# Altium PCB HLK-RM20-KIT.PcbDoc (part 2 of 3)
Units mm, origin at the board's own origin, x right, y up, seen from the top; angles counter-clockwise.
Board outline 152 x 109 mm, 2 copper layers (Top Layer, Bottom Layer), stack 0.325 mm thick; 212 components, 285 nets, 988 pads, 747 vias.
Unrouted connection lines stored in the file: 195.
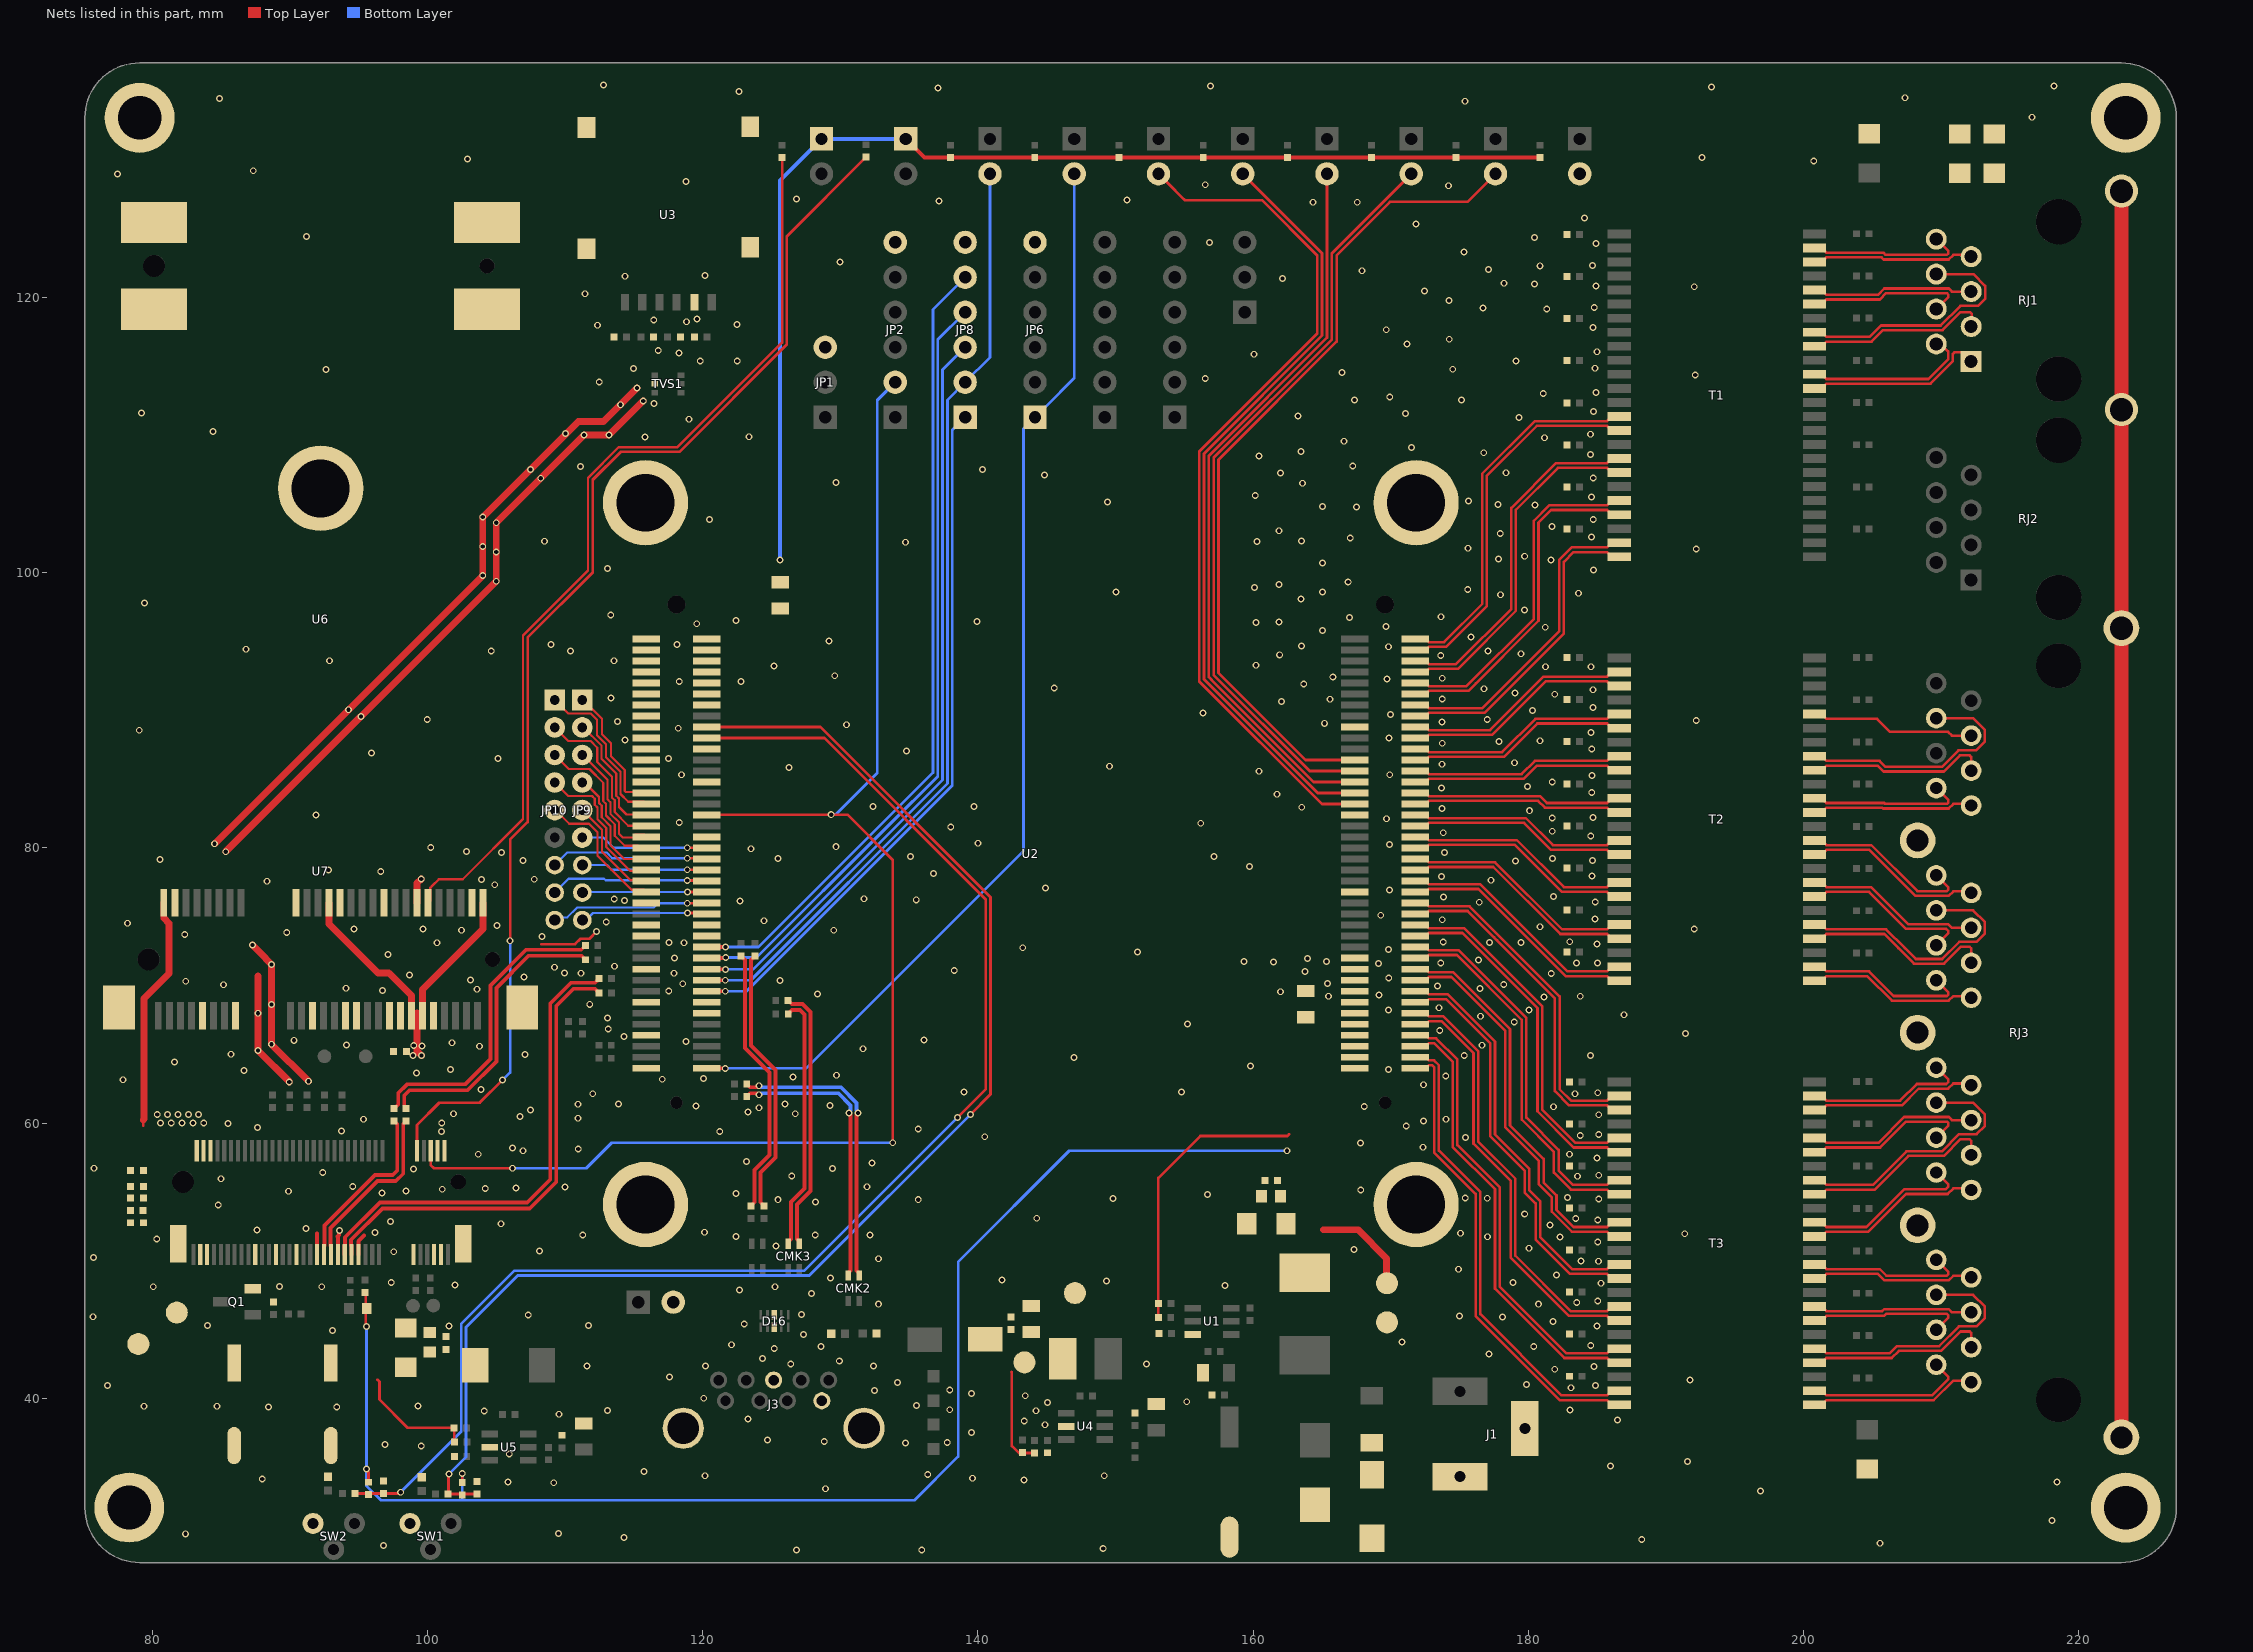
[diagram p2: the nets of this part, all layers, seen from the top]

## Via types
v1: diameter 0.5, hole 0.3, Top Layer to Bottom Layer, tented both sides, 747 vias

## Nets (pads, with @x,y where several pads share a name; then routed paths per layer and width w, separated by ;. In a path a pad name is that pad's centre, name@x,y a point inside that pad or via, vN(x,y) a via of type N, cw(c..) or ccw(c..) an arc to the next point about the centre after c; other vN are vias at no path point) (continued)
5G_SSUSB_RX_N: R64.1 U7.29 | length 34.3
  Top Layer w0.283: U7.29@94.475,50.45 94.475,51.075 94.443,51.107 94.443,51.519 96.721,53.797 107.423,53.797 109.351,55.725 109.351,68.519 110.594,69.762 112.154,69.762 112.343,69.574 R64.1@112.451,69.466
5G_SSUSB_RX_P: R65.1 U7.31 | length 35
  Top Layer w0.283: U7.31@93.975,50.45 93.975,51.075 94.007,51.107 94.007,51.699 96.541,54.233 107.242,54.233 108.915,55.905 108.915,68.699 110.414,70.198 112.177,70.198 112.343,70.364 112.343,70.386 R65.1@112.451,70.495
5G_SSUSB_TX_N: C68.1 R66.1 | length 21.3
  Top Layer w0.283: 98.304,61.354 98.304,61.995 98.691,62.382 102.908,62.382 104.994,64.469 104.994,69.828 107.328,72.162 111.173,72.162 R66.1@111.467,71.868
5G_SSUSB_TX_P: C67.1 R67.1 | length 22.4
  Top Layer w0.283: C67.1@97.574,61.062 97.869,61.357 97.869,62.176 98.511,62.818 102.727,62.818 104.559,64.649 104.559,70.009 107.147,72.597 111.164,72.597 R67.1@111.462,72.895
5G_USB_TX_N: C68.2 U7.35 | length 12.8
  Top Layer w0.283: U7.35@92.975,50.45 92.975,51.075 92.943,51.107 92.943,52.37 96.351,55.778 97.687,55.778 98.228,56.319 98.228,59.931 C68.2@98.447,60.15
5G_USB_TX_P: C67.2 U7.37 | length 12.7
  Top Layer w0.283: U7.37@92.475,50.45 92.475,51.075 92.507,51.107 92.507,52.551 96.171,56.214 97.466,56.214 97.793,56.541 97.793,59.928 C67.2@97.574,60.147
+3.3V: C2.2 C6.2 C8.2 C9.2 C10.1 C28.1 D14.1 D19.1 D20.1 L1.2 R2.1 R13.2 R16.1 R17.2 R20.2 R23.2 R26.2 R28.2 R29.1 R31.2 R34.2 R35.2 TP4.1 U2.A1 U2.A3 U2.A5 U2.A7 U2.A9 U2.A11 U2.B63 U2.B65 U2.B67 U2.B69 U2.B71 U2.B73 U2.B75 U2.B77 U2.B79 | length 216.7
  Top Layer w0.2: R28.2@95.463,47.689 95.509,47.643 95.509,45.258 v1(95.555,45.212) ; v1(95.555,34.849) 95.555,34.768 95.706,34.617 R29.1@95.706,33.9 ; R16.1@102.515,33.87 v1(102.514,34.544) ; R2.1@153.104,45.877 153.104,56 156.159,59.055 162.484,59.055 162.611,59.182
  Top Layer w0.3: D20.1@134.748,131.521 136.106,130.163 R35.2@138.002,130.163 R34.2@144.124,130.163 R31.2@150.245,130.163 R26.2@156.367,130.163 R23.2@162.488,130.163 R20.2@168.609,130.163 R17.2@174.731,130.163 R13.2@180.852,130.163
  Top Layer w0.5: 165.1,52.248 167.615,52.248 169.697,50.165 169.697,48.387 TP4.1@169.723,48.362
  Bottom Layer w0.2: v1(95.555,45.212) v1(95.555,34.849) 95.555,33.638 96.604,32.588 102.511,32.588 ; v1(102.514,34.544) 102.511,34.541 102.511,32.588 ; v1(162.458,57.988) 146.634,57.988 138.557,49.911 138.557,35.763 135.382,32.588 102.511,32.588
  Bottom Layer w0.3: v1(125.603,100.914) 125.603,128.499 D14.1@128.626,131.521 D20.1@134.748,131.521
+3.8V: C17.1 C20.2 C21.2 C22.1 C31.1 C61.1 C62.1 C63.1 C64.1 C65.1 C66.1 D15.2 L2.2 R6.1 TP1.1 U6.2 U6.24 U6.39 U6.41 U6.52 U7.2 U7.4 U7.70 U7.72 U7.74 | length 50.3
  Top Layer w0.2: 79.337,59.817 79.337,60.223 ; 96.355,41.351 96.507,41.199 96.507,39.903 98.56,37.85 R6.1@101.918,37.85 101.938,37.83 101.938,36.855 C20.2@101.957,36.836
  Top Layer w0.5: 79.337,60.223 79.401,60.288 79.401,69.051 81.212,70.862 81.212,74.519 80.829,74.902 80.829,75.996 U6.2@80.825,76 ; U6.24@92.825,76 92.825,74.472 96.393,70.904 97.18,70.904 98.821,69.263 U6.39@98.821,67.804 ; 99.225,67.996 99.225,65.223 v1(99.547,64.9) ; U6.41@99.625,67.8 99.625,69.702 104.025,74.102 U6.52@104.025,76
  other v1: 101.011,59.392 80.581,59.995 81.368,59.995 82.155,59.995 82.942,59.995 83.729,59.995 101.031,60.001 80.352,60.613 81.105,60.613 81.858,60.613 82.611,60.613 83.364,60.613 98.945,64.904 99.598,65.607 98.995,65.63
+4.5V~18V: D1.1 D2.2 F2.2
+5V: C23.2 C24.2 C25.1 D3.1 L4.2 R10.1 TP7.1 | length 7.3
  Top Layer w0.2: 142.443,41.91 142.46,41.893 142.46,36.536 142.971,36.026 143.23,36.026 R10.1@144.119,36.026
DZSS_RX_N: CMK3.1 R71.1 | length 19.3
  Top Layer w0.283: R71.1@126.205,68.915 126.313,68.806 126.313,68.805 126.479,68.639 127.252,68.639 127.816,68.075 127.816,55.058 126.837,54.078 126.837,51.586 127.019,51.404 CMK3.1@127.019,51.229
DZSS_RX_P: CMK3.2 R70.1 | length 18.6
  Top Layer w0.283: R70.1@126.206,67.928 126.314,68.037 126.314,68.038 126.48,68.204 127.071,68.204 127.381,67.894 127.381,55.238 126.401,54.258 126.401,51.585 126.219,51.403 CMK3.2@126.219,51.229
DZSS_TX_N: C33.2 R69.1 | length 19.6
  Top Layer w0.283: R69.1@123.796,72.137 123.687,72.029 123.667,72.029 123.501,71.863 123.501,65.631 125.276,63.856 125.276,57.498 124.197,56.419 124.197,54.247 C33.2@124.458,53.986
DZSS_TX_P: C32.2 R68.1 | length 19.6
  Top Layer w0.283: R68.1@122.771,72.137 122.879,72.029 122.9,72.029 123.066,71.863 123.066,65.451 124.841,63.675 124.841,57.678 123.762,56.599 123.762,54.247 C32.2@123.501,53.986
DZUSB_D_N: CMK2.3 R72.2 | length 21.2
  Top Layer w0.283: R72.2@123.193,62.844 123.432,62.604 123.914,62.604 124.023,62.713 v1(124.082,62.713) ; v1@131.18,60.577 131.18,49.274 131.362,49.092 CMK2.3@131.362,48.917
  Bottom Layer w0.283: v1(124.082,62.713) 124.14,62.713 124.249,62.604 130.044,62.604 131.18,61.468 131.18,60.911 131.289,60.803 v1(131.289,60.744)
DZUSB_D_P: CMK2.4 R73.2 | length 20.6
  Top Layer w0.283: R73.2@123.193,61.929 123.432,62.169 123.914,62.169 124.023,62.06 v1(124.082,62.06) ; CMK2.4@130.563,48.917 130.563,49.092 130.745,49.274 130.745,60.577 130.636,60.685 v1(130.636,60.744)
  Bottom Layer w0.283: v1(124.082,62.06) 124.14,62.06 124.249,62.169 129.864,62.169 130.745,61.288 130.745,60.911 130.636,60.803 v1(130.636,60.744)
ESW_A_P1_TXV_N: T3.23 U2.A4 | length 34
  Top Layer w0.188: U2.A4@171.786,64.783 172.536,64.783 172.766,64.553 173.141,64.553 173.492,64.202 173.492,58.008 176.512,54.988 176.512,46.108 182.415,40.206 185.728,40.206 185.838,40.316 185.838,40.319 186.064,40.545 T3.23@186.594,40.545
ESW_A_P1_TXV_P: T3.24 U2.A2 | length 33.8
  Top Layer w0.188: U2.A2@171.786,63.983 172.536,63.983 172.766,64.213 173,64.213 173.152,64.061 173.152,57.867 176.171,54.847 176.171,46.123 176.171,45.967 182.274,39.865 185.728,39.865 185.838,39.755 185.838,39.751 186.064,39.525 T3.24@186.453,39.525
ESW_A_P2_TXV_N: T3.11 U2.A20 | length 28.4
  Top Layer w0.188: U2.A20@171.786,71.183 172.536,71.183 172.766,70.953 174.547,70.953 178.664,66.836 178.664,59.836 181.101,57.399 181.101,55.689 182.042,54.749 182.042,53.696 183.292,52.446 185.728,52.446 185.838,52.556 185.838,52.559 186.064,52.785 T3.11@186.594,52.785
ESW_A_P2_TXV_P: T3.12 U2.A18 | length 28.4
  Top Layer w0.188: U2.A18@171.786,70.383 172.536,70.383 172.766,70.613 174.406,70.613 178.323,66.695 178.323,59.695 180.761,57.258 180.761,55.548 181.701,54.608 181.701,53.555 183.151,52.105 185.728,52.105 185.838,51.995 185.838,51.991 186.064,51.765 T3.12@186.594,51.765
ESW_A_P3_TXV_N: T2.23 U2.A36 | length 17.7
  Top Layer w0.188: U2.A36@171.786,77.583 172.536,77.583 172.766,77.353 176.514,77.353 182.847,71.021 185.728,71.021 185.838,71.131 185.838,71.134 186.064,71.36 T2.23@186.594,71.36
ESW_A_P3_TXV_P: T2.24 U2.A34 | length 17.7
  Top Layer w0.188: U2.A34@171.786,76.783 172.536,76.783 172.766,77.013 176.373,77.013 182.706,70.68 185.728,70.68 185.838,70.57 185.838,70.566 186.064,70.34 T2.24@186.594,70.34
ESW_A_P4_TXV_N: T2.11 U2.A52 | length 15.3
  Top Layer w0.188: U2.A52@171.786,83.983 172.536,83.983 172.766,83.753 180.853,83.753 181.346,83.261 185.728,83.261 185.838,83.371 185.838,83.374 186.064,83.6 T2.11@186.594,83.6
ESW_A_P4_TXV_P: T2.12 U2.A50 | length 15.3
  Top Layer w0.188: U2.A50@171.786,83.183 172.536,83.183 172.766,83.413 180.712,83.413 181.205,82.92 185.728,82.92 185.838,82.81 185.838,82.806 186.064,82.58 T2.12@186.594,82.58
ESW_A_P5_TXV_N: T1.23 U2.A68 | length 22.9
  Top Layer w0.188: U2.A68@171.786,90.383 172.536,90.383 172.766,90.153 176.653,90.153 182.235,95.735 182.235,100.928 183.142,101.836 185.728,101.836 185.838,101.946 185.838,101.949 186.064,102.175 T1.23@186.594,102.175
ESW_A_P5_TXV_P: T1.24 U2.A66 | length 22.9
  Top Layer w0.188: U2.A66@171.786,89.583 172.536,89.583 172.766,89.813 176.794,89.813 182.575,95.594 182.575,100.787 183.283,101.495 185.728,101.495 185.838,101.385 185.838,101.381 186.064,101.155 T1.24@186.594,101.155
ESW_B_P1_TXV_N: T3.20 U2.A8 | length 32.4
  Top Layer w0.188: U2.A8@171.786,66.383 172.536,66.383 172.766,66.153 173.296,66.153 174.84,64.609 174.84,58.41 177.912,55.338 177.912,48.115 182.761,43.266 185.728,43.266 185.838,43.376 185.838,43.379 186.064,43.605 T3.20@186.594,43.605
ESW_B_P1_TXV_P: T3.21 U2.A6 | length 32.4
  Top Layer w0.188: U2.A6@171.786,65.583 172.536,65.583 172.766,65.813 173.155,65.813 174.5,64.468 174.5,58.269 177.571,55.197 177.571,47.974 182.62,42.925 185.728,42.925 185.838,42.815 185.838,42.811 186.064,42.585 T3.21@186.594,42.585
ESW_B_P2_TXV_N: T3.8 U2.A24 | length 27.2
  Top Layer w0.188: U2.A24@171.786,72.783 172.536,72.783 172.766,72.553 174.947,72.553 179.857,67.643 179.857,60.393 182.194,58.056 182.194,56.54 183.229,55.506 185.728,55.506 185.838,55.616 185.838,55.619 186.064,55.845 T3.8@186.594,55.845
ESW_B_P2_TXV_P: T3.9 U2.A22 | length 27.2
  Top Layer w0.188: U2.A22@171.786,71.983 172.536,71.983 172.766,72.213 174.806,72.213 179.517,67.502 179.517,60.252 181.854,57.915 181.854,56.399 183.088,55.165 185.728,55.165 185.838,55.055 185.838,55.051 186.064,54.825 T3.9@186.594,54.825
ESW_B_P3_TXV_N: T2.20 U2.A40 | length 17.1
  Top Layer w0.188: U2.A40@171.786,79.183 172.536,79.183 172.766,78.953 177.587,78.953 182.459,74.081 185.728,74.081 185.838,74.191 185.838,74.194 186.064,74.42 T2.20@186.594,74.42
ESW_B_P3_TXV_P: T2.21 U2.A38 | length 17.1
  Top Layer w0.188: U2.A38@171.786,78.383 172.536,78.383 172.766,78.613 177.446,78.613 182.318,73.74 185.728,73.74 185.838,73.63 185.838,73.626 186.064,73.4 T2.21@186.594,73.4
ESW_B_P4_TXV_N: T2.8 U2.A56 | length 15.4
  Top Layer w0.188: U2.A56@171.786,85.583 172.536,85.583 172.766,85.353 179.511,85.353 180.478,86.321 185.728,86.321 185.838,86.431 185.838,86.434 186.064,86.66 T2.8@186.594,86.66
ESW_B_P4_TXV_P: T2.9 U2.A54 | length 15.4
  Top Layer w0.188: U2.A54@171.786,84.783 172.536,84.783 172.766,85.013 179.652,85.013 180.619,85.98 185.728,85.98 185.838,85.87 185.838,85.866 186.064,85.64 T2.9@186.594,85.64
ESW_B_P5_TXV_N: T1.20 U2.A72 | length 24.7
  Top Layer w0.188: U2.A72@171.786,91.983 172.536,91.983 172.766,91.753 175.497,91.753 180.391,96.647 180.391,103.773 181.513,104.896 185.728,104.896 185.838,105.006 185.838,105.009 186.064,105.235 T1.20@186.594,105.235
ESW_B_P5_TXV_P: T1.21 U2.A70 | length 25.6
  Top Layer w0.188: U2.A70@171.786,91.183 172.536,91.183 172.766,91.413 175.638,91.413 ; 176.189,91.964 175.638,91.413 ; T1.21@186.735,104.215 T1.21@186.594,104.215 186.064,104.215 185.838,104.441 185.838,104.445 185.728,104.555 181.654,104.555 180.731,103.632 180.731,96.506 175.638,91.413
ESW_C_P1_TXV_N: T3.17 U2.A12 | length 31
  Top Layer w0.188: U2.A12@171.786,67.983 172.536,67.983 172.766,67.753 173.823,67.753 176.352,65.224 176.352,64.237 ; 176.352,64.237 176.352,58.648 179.045,55.955 179.045,50.368 183.076,46.337 183.087,46.326 185.728,46.326 185.838,46.436 185.838,46.439 186.064,46.665 T3.17@186.594,46.665
ESW_C_P1_TXV_P: T3.18 U2.A10 | length 31
  Top Layer w0.188: U2.A10@171.786,67.183 172.536,67.183 172.766,67.413 173.682,67.413 176.012,65.083 176.012,64.096 176.012,58.507 178.704,55.814 178.704,50.227 178.804,50.128 182.946,45.985 185.728,45.985 185.838,45.875 185.838,45.871 186.064,45.645 T3.18@186.594,45.645
ESW_C_P2_TXV_N: T3.5 U2.A28 | length 25.9
  Top Layer w0.188: U2.A28@171.786,74.383 172.536,74.383 172.766,74.153 175.347,74.153 181,68.5 181,61 183.434,58.566 185.728,58.566 185.838,58.676 185.838,58.679 186.064,58.905 T3.5@186.594,58.905
ESW_C_P2_TXV_P: T3.6 U2.A26 | length 25.8
  Top Layer w0.188: U2.A26@171.786,73.583 172.536,73.583 172.766,73.813 175.206,73.813 180.66,68.359 180.66,60.859 183.293,58.225 185.728,58.225 185.838,58.115 185.838,58.111 186.064,57.885 T3.6@186.453,57.885
ESW_C_P3_TXV_N: T2.17 U2.A44 | length 16.5
  Top Layer w0.188: U2.A44@171.786,80.783 172.536,80.783 172.766,80.553 179.162,80.553 182.574,77.141 185.728,77.141 185.838,77.251 185.838,77.254 186.064,77.48 T2.17@186.594,77.48
ESW_C_P3_TXV_P: T2.18 U2.A42 | length 16.5
  Top Layer w0.188: U2.A42@171.786,79.983 172.536,79.983 172.766,80.213 179.021,80.213 182.433,76.8 185.728,76.8 185.838,76.69 185.838,76.686 186.064,76.46 T2.18@186.594,76.46
ESW_C_P4_TXV_N: T2.5 U2.A60 | length 16.1
  Top Layer w0.188: U2.A60@171.786,87.183 172.536,87.183 172.766,86.953 178.089,86.953 180.516,89.381 185.728,89.381 185.838,89.491 185.838,89.494 186.064,89.72 T2.5@186.594,89.72
ESW_C_P4_TXV_P: T2.6 U2.A58 | length 16.1
  Top Layer w0.188: U2.A58@171.786,86.383 172.536,86.383 172.766,86.613 178.23,86.613 180.657,89.04 185.728,89.04 185.838,88.93 185.838,88.926 186.064,88.7 T2.6@186.594,88.7
ESW_C_P5_TXV_N: T1.17 U2.A76 | length 25.4
  Top Layer w0.188: U2.A76@171.786,93.583 172.536,93.583 172.766,93.353 174.735,93.353 178.755,97.373 178.755,104.714 181.997,107.956 185.728,107.956 185.838,108.066 185.838,108.069 186.064,108.295 T1.17@186.594,108.295
ESW_C_P5_TXV_P: T1.18 U2.A74 | length 25.4
  Top Layer w0.188: U2.A74@171.786,92.783 172.536,92.783 172.766,93.013 174.876,93.013 179.095,97.232 179.095,104.573 182.138,107.615 185.728,107.615 185.838,107.505 185.838,107.501 186.064,107.275 T1.18@186.594,107.275
ESW_D_P1_TXV_N: T3.14 U2.A16 | length 29.7
  Top Layer w0.188: U2.A16@171.786,69.583 172.536,69.583 172.766,69.353 174.147,69.353 177.571,65.929 177.571,59.179 180.071,56.679 180.071,55.107 180.873,54.305 180.873,51.689 183.177,49.386 185.728,49.386 185.838,49.496 185.838,49.499 186.064,49.725 T3.14@186.594,49.725
ESW_D_P1_TXV_P: T3.15 U2.A14 | length 29.7
  Top Layer w0.188: U2.A14@171.786,68.783 172.536,68.783 172.766,69.013 174.006,69.013 177.231,65.788 177.231,59.038 179.731,56.538 179.731,54.966 180.533,54.164 180.533,51.548 183.036,49.045 185.728,49.045 185.838,48.935 185.838,48.931 186.064,48.705 T3.15@186.594,48.705
ESW_D_P2_TXV_N: T3.2 U2.A32 | length 24.9
  Top Layer w0.188: U2.A32@171.786,75.983 172.536,75.983 172.766,75.753 175.728,75.753 182.27,69.211 182.27,62.459 183.104,61.626 185.728,61.626 185.838,61.736 185.838,61.739 186.064,61.965 T3.2@186.594,61.965
ESW_D_P2_TXV_P: T3.3 U2.A30 | length 24.9
  Top Layer w0.188: U2.A30@171.786,75.183 172.536,75.183 172.766,75.413 175.587,75.413 177.5,73.5 177.73,73.27 181.93,69.07 181.93,62.318 182.963,61.285 185.728,61.285 185.838,61.175 185.838,61.171 186.064,60.945 T3.3@186.594,60.945
ESW_D_P3_TXV_N: T2.14 U2.A48 | length 15.9
  Top Layer w0.188: U2.A48@171.786,82.383 172.536,82.383 172.766,82.153 179.822,82.153 181.775,80.201 185.728,80.201 185.838,80.311 185.838,80.314 186.064,80.54 T2.14@186.594,80.54
ESW_D_P3_TXV_P: T2.15 U2.A46 | length 15.9
  Top Layer w0.188: U2.A46@171.786,81.583 172.536,81.583 172.766,81.813 179.681,81.813 181.634,79.86 185.728,79.86 185.838,79.75 185.838,79.746 186.064,79.52 T2.15@186.594,79.52
ESW_D_P4_TXV_N: T2.2 U2.A64 | length 16.7
  Top Layer w0.188: U2.A64@171.786,88.783 172.536,88.783 172.766,88.553 177.225,88.553 181.112,92.441 185.728,92.441 185.838,92.551 185.838,92.554 186.064,92.78 T2.2@186.594,92.78
ESW_D_P4_TXV_P: T2.3 U2.A62 | length 16.7
  Top Layer w0.188: U2.A62@171.786,87.983 172.536,87.983 172.766,88.213 177.366,88.213 181.253,92.1 185.728,92.1 185.838,91.99 185.838,91.986 186.064,91.76 T2.3@186.594,91.76
ESW_D_P5_TXV_N: T1.14 U2.A80 | length 27.2
  Top Layer w0.188: U2.A80@171.786,95.183 172.536,95.183 172.766,94.953 173.872,94.953 176.647,97.728 176.647,107.197 180.466,111.016 185.728,111.016 185.838,111.126 185.838,111.129 186.064,111.355 T1.14@186.594,111.355
ESW_D_P5_TXV_P: T1.15 U2.A78 | length 27.2
  Top Layer w0.188: U2.A78@171.786,94.383 172.536,94.383 172.766,94.613 174.013,94.613 176.987,97.587 176.987,107.056 180.607,110.675 185.728,110.675 185.838,110.565 185.838,110.561 186.064,110.335 T1.15@186.594,110.335
ESW_P1_LED: D5.2 U2.A57 | length 60.4
  Top Layer w0.2: U2.A57@167.386,86.383 163.807,86.383 157.48,92.71 157.48,108.204 166.066,116.79 166.066,123.065 169.95,126.949 175.574,126.949 D5.2@177.606,128.981
ESW_P2_LED: D6.2 U2.A55 | length 55.5
  Top Layer w0.2: U2.A55@167.386,85.583 164.108,85.583 157.128,92.564 157.128,108.35 165.713,116.936 165.713,123.211 D6.2@171.484,128.981
ESW_P3_LED: D8.2 U2.A53 | length 53.9
  Top Layer w0.2: D8.2@165.361,128.981 165.361,117.082 156.775,108.496 156.775,92.418 156.972,92.221 156.972,92.202 164.391,84.783 U2.A53@167.386,84.783
ESW_P4_LED_0: D9.2 U2.A51 | length 57.1
  Top Layer w0.2: D9.2@159.238,128.981 165.009,123.211 165.009,117.228 156.423,108.642 156.423,92.253 164.692,83.983 U2.A51@167.386,83.983
ESW_P5_LED_0: D10.2 U2.A49 | length 63.5
  Top Layer w0.2: D10.2@153.116,128.981 153.752,128.345 154.965,127.132 155.024,127.073 155.107,127.073 160.648,127.073 164.656,123.065 164.656,117.374 156.07,108.788 156.07,92.107 164.994,83.183 U2.A49@167.386,83.183
FULL_CARD_POWER_OFF#: JP2.2 U2.B48 U7.6 | length 104.5
  Top Layer w0.2: U7.6@100.225,58 100.225,56.963 100.469,56.718 v1(106.165,56.718) ; U2.B48@120.286,82.383 120.315,82.412 v1(129.331,82.412) 130.516,82.412 133.807,79.121 v1(133.807,58.572)
  Bottom Layer w0.2: v1(106.165,56.718) 111.531,56.718 113.386,58.572 v1(133.807,58.572) ; v1(129.331,82.412) 129.361,82.442 129.678,82.442 132.675,85.438 132.675,112.533 JP2.2@133.985,113.843
GBE_LED0: D13.2 JP8.2 U2.B18 | length 69
  Top Layer w0.283: U2.B18@120.286,70.383 121.628,70.383 v1(121.634,70.377)
  Bottom Layer w0.2: v1(121.634,70.377) 123.482,70.377 137.78,84.675 137.78,112.557 JP8.2@139.065,113.843 140.871,115.649 D13.2@140.871,128.981
GBE_LED1: D11.2 JP6.1 U2.B2 | length 80.3
  Top Layer w0.283: U2.B2@120.286,63.983 121.628,63.983 v1(121.634,63.977)
  Bottom Layer w0.2: v1(121.634,63.977) 127.489,63.977 143.299,79.787 143.299,110.457 144.895,112.053 146.993,114.151 D11.2@146.993,128.981
GND: C2.1 C3.2 C4.1 C5.2 C6.1 C9.1 C10.2 C11.2 C12.2 C13.2 C14.1 C16.2 C17.2 C18.1 C19.2 C21.1 C22.2 C24.1 C25.2 C26.1 C27.1 C28.2 C30.1 C31.2 C34.2 C35.1 C36.1 C37.1 C38.1 C39.1 C40.1 C41.1 C42.1 C43.1 C44.1 C45.1 C46.1 C47.1 C48.1 C49.1 C50.1 C51.1 C52.1 C53.1 C54.1 C55.1 C56.1 C57.1 C58.1 C59.1 C60.2 C61.2 C62.2 C63.2 C64.2 C65.2 C66.2 D2.1 D4.2 D7.1 D12.1 D15.1 D16.3 D16.8 D17.1 D18.1 J1.2 J1.3 J3.4 J3.7 J3.10 J3.11 J5.1 J6.1 J7.1 J8.1 JP1.3 JP2.6 JP5.2 JP6.6 JP8.6 Q1.2 R5.2 R7.2 R12.2 R14.1 R44.1 SW1.1 SW2.1 TP2.1 TP6.1 TP10.1 TVS1.2 U1.3 U2.0 U2.A13 U2.A15 U2.A17 U2.A19 U2.A21 U2.A33 U2.A47 U2.A63 U2.B1 U2.B7 U2.B12 U2.B13 U2.B14 U2.B19 U2.B25 U2.B26 U2.B27 U2.B28 U2.B31 U2.B44 U2.B53 U2.B54 U2.B55 U2.B57 U2.B59 U2.B60 U2.B61 U2.B68 U2.B70 U2.B72 U2.B74 U2.B76 U2.B78 U2.B80 U3.0 U3.1 U4.2 U5.2 U6.4 U6.9 U6.15 U6.18 U6.21 U6.26 U6.27 U6.29 U6.34 U6.35 U6.37 U6.40 U6.43 U6.50 U6.55 U6.56 U6.63 U6.64 U6.65 U6.66 U7.0 U7.3 U7.5 U7.11 U7.27 U7.33 U7.39 U7.45 U7.51 U7.57 U7.71 U7.73 U7.76 U7.77 | length 124.7
  Top Layer w0.2: 108.254,73 110.71,73 111.107,73.397 111.751,73.397 v1(112.268,73.914)
  Top Layer w0.3: 91.973,51.968 91.975,51.967 U7.39@91.975,50.45 ; U7.33@93.475,50.45 93.475,51.762 93.472,51.765 93.561,51.854 93.561,52.159 v1(93.599,52.197) ; U7.27@94.975,50.45 94.975,51.414 95.377,51.816
  Top Layer w0.5: v1(84.518,80.296) v1(104.009,99.787) v1(104.009,104.039) 110.951,110.981 112.787,110.981 v1(115.228,113.422) ; v1(85.331,79.719) v1(104.991,99.38) v1(104.991,103.632) v1(111.358,109.999) v1(113.194,109.999) v1(115.669,112.474) ; v1(87.266,72.928) 88.249,71.945 88.249,71.936 v1(88.667,71.517) v1(88.667,65.727) v1(91.351,63.043) ; 87.685,70.688 v1(87.685,65.274) 89.946,63.013 v1(89.946,62.995) ; U6.40@99.225,76 99.229,76.004 99.229,77.436 v1(99.543,77.749)
  other v1: 126.822,28.981 135.915,28.981 149.098,29.083 96.799,29.312 205.562,29.464 188.239,29.743 114.275,29.87 82.398,30.15 109.525,30.175 218.059,31.115 196.875,33.274 128.905,33.426 109.169,33.858 105.842,33.909 218.415,33.909 143.332,34.061 87.986,34.138 139.598,34.188 120.167,34.366 149.174,34.366 136.347,34.468 115.722,34.671 185.979,35.077 191.567,35.408 105.93,35.943 99.543,36.525 96.901,36.652 134.722,36.754 137.77,36.779 128.829,36.855 124.714,36.957 139.522,37.516 144.856,38.075 143.358,38.354 186.487,38.43 123.292,38.506 109.55,38.837 104.115,39.065 144.221,39.091 113.081,39.116 183.032,39.141 137.947,39.167 88.443,39.37 93.396,39.37 79.4,39.421 84.684,39.421 99.314,39.446 135.534,39.472 145.059,39.7 155.169,39.751 120.066,40.005 143.434,40.183 139.522,40.335 132.486,40.564 137.947,40.615 183.109,40.767 76.733,40.919 184.887,40.919 179.857,40.996 134.137,41.148 191.745,41.326 117.577,41.554 181.915,42.113 184.76,42.316 111.582,42.342 120.193,42.342 132.41,42.342 126.39,42.494 152.248,42.494 129.921,42.697 124.333,42.901 177.14,43.205 125.197,43.612 128.6,43.764 180.391,43.764 184.531,43.84 122.098,43.891 170.815,44.094 127.305,44.628 93.091,44.933 101.549,45.263 184.988,45.263 83.998,45.288 111.684,45.288 123.012,45.39 181.788,45.568 178.13,45.898 75.692,45.923 175.006,45.974 107.315,46.05 127.178,46.076 132.766,46.838 180.721,46.838 183.515,46.965 185.039,47.066 127.889,47.625 122.657,47.879 80.061,48.108 92.304,48.108 125.247,48.108 89.23,48.133 157.937,48.184 101.981,48.235 185.268,48.362 97.358,48.412 178.892,48.412 149.327,48.514 141.757,48.59 129.286,48.743 182.042,48.971 174.93,49.378 185.09,49.962 183.82,49.987 132.766,50.14 75.717,50.241 97.536,50.648 108.128,50.698 167.335,50.8 180.035,50.902 125.324,51.054 185.039,51.359 80.315,51.587 182.296,51.714 177.038,51.74 122.403,51.765 111.277,51.867 128.168,51.867 132.156,51.867 191.36,51.955 175.057,51.994 96.19,52.045 120.117,52.07 87.605,52.222 91.161,52.349 181.559,52.603 105.334,52.68 97.307,52.857 185.039,52.959 183.439,53.061 144.272,53.086 179.73,53.391 84.785,54.051 128.194,54.254 125.476,54.432 135.661,54.432 185.115,54.483 149.809,54.508 177.013,54.534 175.412,54.559 182.855,54.585 156.667,54.813 122.403,54.889 96.698,54.915 89.891,55.042 98.425,55.067 167.818,55.143 101.067,55.194 104.191,55.245 106.426,55.27 109.982,55.347 131.928,55.372 94.564,55.397 84.988,55.956 183.566,56.134 126.467,56.159 185.115,56.21 92.38,56.413 98.984,56.667 129.438,56.693 75.743,56.718 132.309,57.099 123.165,57.201 184.988,57.455 103.683,57.734 182.982,57.734 106.934,57.988 110.947,58.115 106.172,58.191 172.339,58.242 167.792,58.547 175.438,58.953 140.487,59.004 183.769,59.106 185.115,59.182 121.234,59.385 93.751,59.411 135.661,59.563 87.63,59.69 171.12,59.792 85.496,59.969 172.364,60.147 95.352,60.274 174.003,60.282 110.922,60.35 106.705,60.477 185.115,60.604 101.879,60.681 126.721,60.681 123.292,60.808 107.467,60.96 124.079,61.112 181.813,61.189 168.072,61.214 119.507,61.239 129.235,61.265 110.922,61.366 113.868,61.392 125.984,61.392 183.388,62.128 112.003,62.135 185.039,62.205 138.989,62.255 154.788,62.255 103.886,62.433 172.364,62.789 77.876,63.144 117.053,63.183 120.04,63.246 126.543,63.348 173.99,63.424 129.718,63.475 99.187,63.652 86.665,63.83 101.676,63.906 169.824,63.906 159.817,64.135 81.61,64.44 146.964,64.77 175.336,64.922 184.506,64.922 107.086,64.973 85.725,64.999 131.648,65.405 103.784,65.583 176.625,65.659 94.107,65.684 101.778,65.837 118.77,65.938 90.297,66.015 136.068,66.04 114.275,66.294 191.414,66.523 173.558,66.726 113.132,66.827 155.219,67.208 178.968,67.335 113.081,67.64 176.53,67.767 186.944,67.869 87.685,67.981 169.824,68.224 180.035,68.224 173.507,68.377 88.667,68.622 111.785,68.631 181.127,69.164 165.481,69.215 183.769,69.215 169.139,69.317 128.346,69.393 161.976,69.545 117.526,69.596 96.723,69.621 103.581,69.723 176.479,69.774 94.056,69.799 173.406,69.952 85.166,70.053 178.206,70.079 118.542,70.129 165.405,70.155 82.423,70.307 125.603,70.358 103.124,70.409 169.85,70.536 107.01,70.612 98.679,70.764 181.661,70.866 111.15,70.891 117.907,70.891 109.957,70.917 163.754,71.018 138.278,71.095 109.22,71.323 113.589,71.399 169.113,71.603 173.634,71.628 183.49,71.628 185.014,71.628 161.468,71.704 159.334,71.755 165.329,71.755 176.378,71.857 163.957,71.958 117.932,71.984 97.13,72.263 151.587,72.441 169.824,72.619 143.256,72.746 184.988,73.025 100.686,73.101 118.643,73.101 117.551,73.127 177.165,73.127 179.451,73.127 173.812,73.152 183.007,73.177 108.306,73.558 82.347,73.711 89.764,73.863 102.464,74.016 129.515,74.016 192.049,74.092 94.64,74.117 99.67,74.117 180.848,74.27 105.054,74.346 78.181,74.524 112.979,74.625 124.435,74.701 173.736,74.778 184.836,74.828 169.266,75.108 176.428,76.048 184.861,76.073 122.707,76.149 114.307,76.182 135.509,76.225 113.563,76.276 131.724,76.302 173.838,76.429 181.813,76.479 169.901,76.937 144.907,77.089 104.877,77.318 88.316,77.572 177.292,77.648 103.911,77.699 107.747,77.724 173.685,77.927 184.633,77.953 136.779,78.13 96.596,78.283 92.786,78.384 159.741,78.638 179.07,79.045 106.934,79.096 184.658,79.096 80.543,79.146 125.476,79.223 181.762,79.223 135.103,79.375 157.15,79.375 105.359,79.654 173.914,79.654 102.819,79.731 123.495,79.934 100.228,80.035 129.667,80.086 169.901,80.239 140.005,80.34 184.531,80.874 173.812,81.102 181.737,81.204 138.024,81.509 156.185,81.788 118.288,81.839 169.697,82.118 181.737,82.169 184.683,82.22 91.897,82.398 180.086,82.702 173.711,82.855 163.525,82.956 132.359,83.007 139.7,83.007 161.722,83.896 184.607,84.023 173.685,84.353 179.934,84.455 181.737,84.785 184.633,85.268 118.44,85.319 169.926,85.319 160.426,85.573 126.263,85.852 149.555,85.928 173.711,86.081 178.994,86.182 105.105,86.487 117.5,86.487 95.936,86.893 134.798,87.046 184.607,87.173 173.736,87.605 177.876,87.732 180.848,87.782 114.351,87.833 169.875,87.986 184.556,88.392 79.045,88.544 118.212,88.697 130.454,88.951 165.176,89.052 173.711,89.154 113.792,89.179 192.202,89.256 99.974,89.332 177.013,89.332 95.161,89.549 169.977,89.687 156.362,89.814 180.289,89.992 94.263,90.041 184.683,90.195 162.052,90.627 165.583,90.805 173.736,90.83 113.335,90.881 181.915,91.161 179.019,91.262 184.683,91.491 176.784,91.567 145.542,91.618 163.678,91.897 118.288,92.1 122.784,92.1 169.723,92.278 173.736,92.329 165.786,92.431 129.591,92.507 181.254,93.167 184.556,93.167 125.171,93.218 160.198,93.269 92.862,93.599 113.538,93.599 173.634,93.98 161.925,94.031 179.451,94.107 104.623,94.31 110.388,94.31 177.063,94.31 86.792,94.437 169.824,94.615 163.5,94.666 108.966,94.793 118.135,94.793 129.184,95.021 175.819,95.326 165.049,95.809 181.229,96.037 169.647,96.088 119.558,96.291 160.198,96.368 161.874,96.418 139.929,96.444 122.403,96.52 166.986,96.733 173.66,96.799 113.309,96.926 179.705,97.282 79.426,97.79 163.474,98.095 177.978,98.4 183.642,98.501 150.038,98.603 165.049,98.603 175.59,98.781 160.096,98.933 161.874,99.136 166.903,99.314 184.734,100.203 113.081,100.305 165.024,100.711 181.635,100.914 177.825,100.99 179.73,101.194 104.991,101.506 192.202,101.727 175.616,101.778 104.009,101.913 134.722,102.21 160.274,102.26 108.509,102.286 163.5,102.311 167.056,102.514 184.582,102.591 177.952,102.845 161.874,103.048 181.712,103.353 120.498,103.861 184.709,103.861 167.513,104.775 165.024,104.8 180.467,104.927 177.8,104.953 149.403,105.131 175.641,105.207 184.582,105.512 160.147,105.613 163.576,106.502 129.667,106.553 108.225,106.865 184.709,106.883 144.831,107.112 161.976,107.239 178.384,107.264 140.335,107.493 107.48,107.51 111.1,107.721 167.234,107.747 160.426,108.483 184.506,108.585 176.759,108.712 163.474,108.814 171.501,109.093 166.599,109.55 181.178,109.804 115.799,109.855 123.368,109.88 184.506,110.058 110.033,110.109 84.404,110.261 118.999,111.15 179.324,111.277 163.246,111.379 171.069,111.557 79.197,111.608 184.734,111.709 114.008,112.202 116.459,112.293 167.361,112.547 175.133,112.547 169.926,112.776 181.077,113.03 184.912,113.081 112.471,113.868 156.515,114.122 192.126,114.376 166.446,114.554 92.608,114.757 174.498,114.783 114.96,114.833 184.836,114.859 119.812,115.392 122.504,115.392 179.095,115.392 160.071,115.875 118.262,115.976 184.988,116.053 116.764,116.154 171.171,116.611 174.244,116.967 169.672,117.653 184.683,117.805 112.344,117.983 122.479,118.034 118.821,118.237 116.434,118.364 119.583,118.44 181.331,119.151 176.708,119.228 184.785,119.278 174.219,119.786 111.43,120.269 172.441,120.472 192.049,120.777 184.912,120.828 180.442,120.98 178.232,121.031 162.128,121.387 114.351,121.539 120.167,121.59 167.894,121.945 177.089,122.022 180.848,122.301 184.658,122.326 129.972,122.58 175.311,123.317 184.912,123.927 156.82,124.003 180.442,124.358 91.211,124.435 171.831,125.349 184.074,125.781 164.338,126.924 167.564,126.924 137.16,127 150.825,127.076 126.822,127.152 174.193,128.118 156.515,128.194 118.77,128.422 77.47,128.981 87.325,129.21 200.736,129.921 102.895,130.073 192.608,130.175 216.611,133.096 175.387,134.264 84.887,134.468 207.366,134.518 122.631,134.976 137.084,135.23 193.319,135.306 156.896,135.382 218.186,135.382 112.776,135.433
GND_EARTH: C40.2 R44.2 RJ1.0 RJ2.0 RJ3.EH | length 90.6
  Top Layer w1: RJ3.EH@223.1,37.162 RJ2.0@223.1,95.972 RJ1.0@223.1,111.852 RJ1.0@223.1,127.732
GPIO40: JP10.4 U2.B37 | length 10.9
  Top Layer w0.16: JP10.4@109.241,84.75 110.223,83.768 111.95,83.768 112.144,83.574 112.144,83.138 112.344,82.937 112.344,82.088 112.982,81.451 112.982,80.058 114.706,78.334 115.836,78.334 U2.B37@115.886,78.383
GPIO41: JP9.5 U2.B35 | length 7.7
  Top Layer w0.16: JP9.5@111.241,82.75 112.669,81.321 112.669,79.71 114.74,77.64 115.829,77.64 U2.B35@115.886,77.583
GPIO42: JP9.4 U2.B39 | length 9.4
  Top Layer w0.16: JP9.4@111.241,84.75 111.41,84.75 112.456,83.703 112.456,83.267 112.657,83.067 112.657,82.218 113.294,81.58 113.294,80.193 114.29,79.197 115.872,79.197 U2.B39@115.886,79.183 ; JP9.4@111.241,85.404 111.658,84.986 JP9.4@111.658,84.728
GPIO43: JP10.5 U2.B33 | length 10.1
  Top Layer w0.16: JP10.5@109.241,82.75 109.301,82.75 110.295,81.755 111.733,81.755 112.344,81.144 112.344,79.426 114.817,76.953 115.716,76.953 U2.B33@115.886,76.783
GPIO44: JP10.3 U2.B41 | length 10.5
  Top Layer w0.16: JP10.3@109.241,86.75 110.258,85.732 111.76,85.732 112.769,84.724 112.769,83.396 112.969,83.196 112.969,82.347 113.607,81.709 113.607,80.881 114.335,80.153 115.266,80.153 U2.B41@115.286,80.133
GPIO45: JP9.3 U2.B43 | length 9.8
  Top Layer w0.16: JP9.3@111.241,86.75 111.274,86.75 113.081,84.943 113.081,83.526 113.281,83.325 113.281,82.476 113.919,81.839 113.919,81.011 114.166,80.764 115.867,80.764 U2.B43@115.886,80.783
  Top Layer w0.2: U2.B43@115.086,80.933 115.736,80.933 U2.B43@115.886,80.783
GPIO46: JP10.2 U2.B45 | length 11.6
  Top Layer w0.16: JP10.2@109.241,88.75 110.223,87.768 111.851,87.768 112.336,87.282 112.336,86.241 113.394,85.184 113.394,83.655 113.594,83.455 113.594,82.606 114.589,81.61 115.859,81.61 U2.B45@115.886,81.583
GPIO47: JP9.2 U2.B47 | length 9.1
  Top Layer w0.16: JP9.2@111.241,88.75 111.31,88.75 112.649,87.412 112.649,86.462 113.706,85.404 113.706,83.785 113.906,83.584 113.906,82.969 114.452,82.423 115.846,82.423 U2.B47@115.886,82.383
GPIO48: JP10.1 U2.B49 | length 11.9
  Top Layer w0.16: JP10.1@109.241,90.75 110.223,89.768 111.858,89.768 112.316,89.31 112.316,88.186 112.961,87.541 112.961,86.591 114.018,85.534 114.018,83.914 114.579,83.353 115.716,83.353 U2.B49@115.886,83.183
GPIO49: JP9.1 U2.B51 | length 8.7
  Top Layer w0.16: JP9.1@111.241,90.75 111.911,90.08 111.988,90.08 112.677,89.391 112.677,88.267 113.332,87.612 113.332,86.662 114.331,85.663 114.331,84.151 114.424,84.057 115.012,84.057 U2.B51@115.086,83.983
GPIO50: JP9.9 U2.B30 | length 9.3
  Top Layer w0.2: v1(118.897,75.26) 120.209,75.26 U2.B30@120.286,75.183
  Bottom Layer w0.16: JP9.9@111.241,74.75 111.514,74.75 112.024,75.26 v1(118.897,75.26)
GPIO51: JP10.9 U2.B32 | length 11.6
  Top Layer w0.2: v1(118.872,75.971) 120.274,75.971 U2.B32@120.286,75.983
  Bottom Layer w0.16: JP10.9@109.241,74.75 109.439,74.948 110.156,74.948 110.865,75.657 116.41,75.657 116.724,75.971 v1(118.872,75.971)
GPIO52: JP9.8 U2.B34 | length 9.1
  Top Layer w0.2: v1(118.897,76.784) 120.285,76.784 U2.B34@120.286,76.783
  Bottom Layer w0.16: JP9.8@111.241,76.75 111.275,76.784 v1(118.897,76.784)
GPIO53: JP10.8 U2.B36 | length 11.5
  Top Layer w0.2: v1(118.872,77.622) 120.247,77.622 U2.B36@120.286,77.583
  Bottom Layer w0.16: JP10.8@109.241,76.75 110.247,77.756 112.82,77.756 112.936,77.64 118.855,77.64 v1(118.872,77.622)
GPIO54: JP9.7 U2.B38 | length 9.2
  Top Layer w0.2: v1(118.872,78.41) 120.26,78.41 U2.B38@120.286,78.383
  Bottom Layer w0.16: JP9.7@111.241,78.75 113.041,78.75 113.382,78.41 v1(118.872,78.41)
GPIO55: JP10.7 U2.B40 | length 11.6
  Top Layer w0.2: v1(118.872,79.248) 120.221,79.248 U2.B40@120.286,79.183
  Bottom Layer w0.16: JP10.7@109.241,78.75 110.148,79.657 113.012,79.657 113.421,79.248 v1(118.872,79.248)
GPIO56: JP9.6 U2.B42 | length 9.4
  Top Layer w0.2: v1(118.872,80.01) 120.259,80.01 U2.B42@120.286,79.983
  Bottom Layer w0.16: JP9.6@111.241,80.75 112.763,80.75 113.503,80.01 v1(118.872,80.01)
GPIO_RESET: C26.2 R16.2 R19.2 U2.B64 | length 100
  Top Layer w0.2: R19.2@101.486,33.043 R19.2@101.487,33.045 ; v1(101.549,34.493) 101.518,34.462 101.518,33.075 R19.2@101.487,33.045 ; C26.2@103.582,33.046 C26.2@103.582,33.046 R19.2@101.487,33.045 ; U2.B64@120.286,88.783 128.539,88.783 140.908,76.414 140.908,62.092 v1(139.446,60.63)
  Bottom Layer w0.2: v1(101.549,34.493) 102.794,35.738 102.794,38.227 102.794,45.161 106.553,48.92 127.737,48.92 v1(139.446,60.63)
GPIO_WPS: C30.2 R29.2 R30.2 U2.B62 | length 101.5
  Top Layer w0.2: R30.2@94.725,33.074 97.864,33.074 97.963,33.172 v1(98.044,33.172) ; U2.B62@120.286,87.983 128.841,87.983 140.556,76.268 140.556,62.45 v1(138.507,60.401)
  Bottom Layer w0.2: v1(98.044,33.172) 102.438,37.567 102.438,45.39 106.321,49.273 127.379,49.273 v1(138.507,60.401)
JTAG_JTCK: JP8.1 U2.B16 | length 51.2
  Top Layer w0.283: U2.B16@120.286,69.583 121.628,69.583 v1(121.634,69.577)
  Bottom Layer w0.2: v1(121.634,69.577) 123.18,69.577 138.132,84.529 138.132,110.37 JP8.1@139.065,111.303
JTAG_JTDI: JP8.4 U2.B22 | length 56.8
  Top Layer w0.283: U2.B22@120.286,71.983 120.312,72.009 121.64,72.009 v1(121.666,72.034)
  Bottom Layer w0.2: v1(121.666,72.034) 123.907,72.034 133.517,81.644 137.075,85.202 137.075,116.933 JP8.4@139.065,118.923
JTAG_JTDO: JP8.3 U2.B20 | length 55.4
  Top Layer w0.283: U2.B20@120.286,71.183 120.292,71.177 121.634,71.177 v1(121.641,71.171)
  Bottom Layer w0.2: v1(121.641,71.171) 123.659,71.171 137.427,84.938 137.427,114.745 JP8.3@138.989,116.307 ; JP8.3@138.684,116.002 JP8.3@138.989,116.307 ; JP8.3@139.065,116.383 JP8.3@138.989,116.307
JTAG_JTMS: JP8.5 U2.B24 | length 58.7
  Top Layer w0.283: U2.B24@120.286,72.783 120.293,72.79 121.634,72.79 v1(121.641,72.796)
  Bottom Layer w0.2: v1(121.641,72.796) 124.054,72.796 136.722,85.465 136.722,119.12 JP8.5@139.065,121.463
LED_5G: R32.1 U7.10 | length 92.8
  Top Layer w0.2: U7.10@99.225,58 99.225,59.858 100.845,61.478 103.785,61.478 105.436,63.129 v1(105.445,63.129) ; 100.897,61.468 103.785,61.468 103.79,61.473 ; v1(106,73.25) 106,80.613 107.273,81.886 107.273,95.292 112,100.019 112,106.75 114.034,108.784 118.302,108.784 126.101,116.582 126.101,124.429 R32.1@131.873,130.201
  Bottom Layer w0.2: v1(105.445,63.129) 106,63.683 v1(106,73.25)
LED_WWAN#: R8.2 U6.42 | length 68.3
  Top Layer w0.178: U6.42@100.025,76 100.19,76.165 100.19,77.089 100.317,77.216 ; 100.317,77.216 100.825,77.724 102.552,77.724 106.931,82.103 106.931,95.433 111.659,100.161 111.659,106.891 113.892,109.125 118.161,109.125 125.759,116.724 R8.2@125.759,130.163
MTXV_P0_A_N: RJ1.2 T1.38 | length 12.1
  Top Layer w0.188: T1.38@200.794,114.415 201.324,114.415 201.55,114.189 201.55,114.186 201.66,114.076 204.062,114.076 209.079,114.076 210.511,115.507 210.511,116.09 209.984,116.617 RJ1.2@209.64,116.617
MTXV_P0_A_P: RJ1.1 T1.37 | length 13.1
  Top Layer w0.188: T1.37@200.794,113.395 201.324,113.395 201.55,113.621 201.55,113.625 201.66,113.735 204.203,113.735 209.22,113.735 210.851,115.366 210.851,115.905 210.961,116.015 211.512,116.015 RJ1.1@212.18,115.347
MTXV_P0_B_N: RJ1.6 T1.41 | length 18.5
  Top Layer w0.188: T1.41@200.794,117.475 201.324,117.475 201.55,117.249 201.55,117.246 201.66,117.136 204.794,117.136 205.625,117.966 209.965,117.966 211.396,119.397 212.681,119.397 213.188,119.904 213.188,120.845 212.336,121.697 RJ1.6@209.64,121.697
MTXV_P0_B_P: RJ1.3 T1.40 | length 13.4
  Top Layer w0.188: T1.40@200.794,116.455 201.324,116.455 201.55,116.681 201.55,116.685 201.66,116.795 204.935,116.795 205.766,117.626 210.106,117.626 211.413,118.933 212.105,118.933 212.215,118.823 212.215,117.923 RJ1.3@212.18,117.887
MTXV_P0_C_N: RJ1.5 T1.44 | length 11.8
  Top Layer w0.188: T1.44@200.794,120.535 201.324,120.535 201.55,120.309 201.55,120.306 201.66,120.196 205.407,120.196 205.861,120.649 210.556,120.649 210.778,120.427 RJ1.5@212.18,120.427
MTXV_P0_C_P: RJ1.4 T1.43 | length 11.5
  Top Layer w0.188: T1.43@200.794,119.515 201.324,119.515 201.55,119.741 201.55,119.745 201.66,119.855 205.548,119.855 206.002,120.309 210.415,120.309 210.526,120.199 210.526,120.043 RJ1.4@209.64,119.157
MTXV_P0_D_N: RJ1.8 T1.47 | length 11.4
  Top Layer w0.188: T1.47@200.794,123.595 201.324,123.595 201.55,123.369 201.55,123.366 201.66,123.256 205.803,123.256 205.961,123.098 210.403,123.098 210.514,123.208 210.514,123.364 RJ1.8@209.64,124.237
MTXV_P0_D_P: RJ1.7 T1.46 | length 11.8
  Top Layer w0.188: T1.46@200.794,122.575 201.324,122.575 201.55,122.801 201.55,122.805 201.66,122.915 205.662,122.915 205.82,122.757 210.544,122.757 210.89,123.103 212.044,123.103 RJ1.7@212.18,122.967
MTXV_P1_A_N: RJ3.A2 T3.26 | length 11.8
  Top Layer w0.188: T3.26@200.794,40.545 201.324,40.545 201.55,40.319 201.55,40.316 201.66,40.206 209.318,40.206 210.517,41.405 210.517,41.56 RJ3.A2@209.64,42.437
MTXV_P1_A_P: RJ3.A1 T3.25 | length 12.2
  Top Layer w0.188: T3.25@200.794,39.525 201.324,39.525 201.55,39.751 201.55,39.755 201.66,39.865 209.459,39.865 210.878,41.284 212.063,41.284 RJ3.A1@212.18,41.167
MTXV_P1_B_N: RJ3.A6 T3.29 | length 18.3
  Top Layer w0.188: T3.29@200.794,43.605 201.324,43.605 201.55,43.379 201.55,43.376 201.66,43.266 206.257,43.266 206.78,43.788 209.859,43.788 211.291,45.219 212.561,45.219 213.176,45.835 213.176,46.66 212.319,47.517 RJ3.A6@209.64,47.517
MTXV_P1_B_P: RJ3.A3 T3.28 | length 13.4
  Top Layer w0.188: T3.28@200.794,42.585 201.324,42.585 201.55,42.811 201.55,42.815 201.66,42.925 206.398,42.925 206.92,43.447 210,43.447 211.404,44.851 212.07,44.851 212.18,44.741 RJ3.A3@212.18,43.707
MTXV_P1_C_N: RJ3.A5 T3.32 | length 11.7
  Top Layer w0.188: T3.32@200.794,46.665 201.324,46.665 201.55,46.439 201.55,46.436 201.66,46.326 205.711,46.326 205.855,46.469 210.556,46.469 210.778,46.247 RJ3.A5@212.18,46.247
MTXV_P1_C_P: RJ3.A4 T3.31 | length 11.4
  Top Layer w0.188: T3.31@200.794,45.645 201.324,45.645 201.55,45.871 201.55,45.875 201.66,45.985 205.852,45.985 205.996,46.129 210.415,46.129 210.526,46.019 210.526,45.863 RJ3.A4@209.64,44.977
MTXV_P1_D_N: RJ3.A8 T3.35 | length 11.5
  Top Layer w0.188: T3.35@200.794,49.725 201.324,49.725 201.55,49.499 201.55,49.496 201.66,49.386 205.535,49.386 206.006,48.914 210.407,48.914 210.517,49.025 210.517,49.18 RJ3.A8@209.64,50.057
MTXV_P1_D_P: RJ3.A7 T3.34 | length 11.9
  Top Layer w0.188: T3.34@200.794,48.705 201.324,48.705 201.55,48.931 201.55,48.935 201.66,49.045 205.394,49.045 205.865,48.574 210.548,48.574 210.878,48.904 212.063,48.904 RJ3.A7@212.18,48.787
MTXV_P2_A_N: RJ3.B2 T3.38 | length 12.5
  Top Layer w0.188: T3.38@200.794,52.785 201.324,52.785 201.55,52.559 201.55,52.556 201.66,52.446 204.566,52.446 207.307,55.187 210.329,55.187 210.517,55.375 210.517,55.53 RJ3.B2@209.64,56.407
MTXV_P2_A_P: RJ3.B1 T3.37 | length 12.9
  Top Layer w0.188: T3.37@200.794,51.765 201.324,51.765 201.55,51.991 201.55,51.995 201.66,52.105 204.707,52.105 207.448,54.846 210.47,54.846 210.878,55.254 212.063,55.254 RJ3.B1@212.18,55.137
MTXV_P2_B_N: RJ3.B6 T3.41 | length 19
  Top Layer w0.188: T3.41@200.794,55.845 201.324,55.845 201.55,55.619 201.55,55.616 201.66,55.506 205.035,55.506 207.481,57.951 210.052,57.951 211.295,59.193 212.565,59.193 213.176,59.805 213.176,60.63 212.319,61.487 RJ3.B6@209.64,61.487
MTXV_P2_B_P: RJ3.B3 T3.40 | length 14.1
  Top Layer w0.188: T3.40@200.794,54.825 201.324,54.825 201.55,55.051 201.55,55.055 201.66,55.165 205.176,55.165 207.622,57.61 210.193,57.61 211.408,58.825 212.07,58.825 212.18,58.715 RJ3.B3@212.18,57.677
MTXV_P2_C_N: RJ3.B5 T3.44 | length 12.4
  Top Layer w0.188: T3.44@200.794,58.905 201.324,58.905 201.55,58.679 201.55,58.676 201.66,58.566 205.428,58.566 207.302,60.439 210.556,60.439 210.778,60.217 RJ3.B5@212.18,60.217
MTXV_P2_C_P: RJ3.B4 T3.43 | length 12.1
  Top Layer w0.188: T3.43@200.794,57.885 201.324,57.885 201.55,58.111 201.55,58.115 201.66,58.225 205.569,58.225 207.443,60.099 210.415,60.099 210.526,59.989 210.526,59.833 RJ3.B4@209.64,58.947
MTXV_P2_D_N: RJ3.B8 T3.47 | length 11.8
  Top Layer w0.188: T3.47@200.794,61.965 201.324,61.965 201.55,61.739 201.55,61.736 201.66,61.626 207.015,61.626 208.227,62.838 210.36,62.838 210.517,62.995 210.517,63.15 RJ3.B8@209.64,64.027
MTXV_P2_D_P: RJ3.B7 T3.46 | length 12.2
  Top Layer w0.188: T3.46@200.794,60.945 201.324,60.945 201.55,61.171 201.55,61.175 201.66,61.285 207.156,61.285 208.368,62.497 210.501,62.497 210.878,62.874 212.063,62.874 RJ3.B7@212.18,62.757
MTXV_P3_A_N: RJ3.C2 T2.26 | length 12
  Top Layer w0.188: T2.26@200.794,71.36 201.324,71.36 201.55,71.134 201.55,71.131 201.66,71.021 204.763,71.021 206.549,69.234 210.407,69.234 210.517,69.345 210.517,69.5 RJ3.C2@209.64,70.377
MTXV_P3_A_P: RJ3.C1 T2.25 | length 12.5
  Top Layer w0.188: T2.25@200.794,70.34 201.324,70.34 201.55,70.566 201.55,70.57 201.66,70.68 204.622,70.68 206.408,68.894 210.548,68.894 210.878,69.224 212.063,69.224 RJ3.C1@212.18,69.107
MTXV_P3_B_N: RJ3.C6 T2.29 | length 18.9
  Top Layer w0.188: T2.29@200.794,74.42 201.324,74.42 201.55,74.194 201.55,74.191 201.66,74.081 206.004,74.081 207.368,72.717 208.164,71.921 210.063,71.921 211.312,73.17 212.571,73.17 213.176,73.775 213.176,74.6 212.319,75.457 RJ3.C6@209.64,75.457
MTXV_P3_B_P: RJ3.C3 T2.28 | length 14
  Top Layer w0.188: T2.28@200.794,73.4 201.324,73.4 201.55,73.626 201.55,73.63 201.66,73.74 205.863,73.74 206.897,72.707 208.023,71.58 210.204,71.58 211.44,72.816 212.07,72.816 212.18,72.706 RJ3.C3@212.18,71.647
MTXV_P3_C_N: RJ3.C5 T2.32 | length 12.8
  Top Layer w0.188: T2.32@200.794,77.48 201.324,77.48 201.55,77.254 201.55,77.251 201.66,77.141 204.911,77.141 207.591,74.461 210.505,74.461 210.778,74.187 RJ3.C5@212.18,74.187
MTXV_P3_C_P: RJ3.C4 T2.31 | length 12.5
  Top Layer w0.188: T2.31@200.794,76.46 201.324,76.46 201.55,76.686 201.55,76.69 201.66,76.8 204.77,76.8 207.45,74.12 210.364,74.12 210.526,73.959 210.526,73.803 RJ3.C4@209.64,72.917
MTXV_P3_D_N: RJ3.C8 T2.35 | length 12.7
  Top Layer w0.188: T2.35@200.794,80.54 201.324,80.54 201.55,80.314 201.55,80.311 201.66,80.201 204.917,80.201 208.263,76.854 210.407,76.854 210.517,76.965 210.517,77.12 RJ3.C8@209.64,77.997
MTXV_P3_D_P: RJ3.C7 T2.34 | length 13.1
  Top Layer w0.188: T2.34@200.794,79.52 201.324,79.52 201.55,79.746 201.55,79.75 201.66,79.86 204.776,79.86 208.122,76.514 210.548,76.514 210.878,76.844 212.063,76.844 RJ3.C7@212.18,76.727
MTXV_P4_A_N: RJ3.D2 T2.38 | length 11.3
  Top Layer w0.188: T2.38@200.794,83.6 201.324,83.6 201.55,83.374 201.55,83.371 201.66,83.261 205.855,83.261 205.912,83.204 210.407,83.204 210.517,83.315 210.517,83.47 RJ3.D2@209.64,84.347
MTXV_P4_A_P: RJ3.D1 T2.37 | length 11.7
  Top Layer w0.188: T2.37@200.794,82.58 201.324,82.58 201.55,82.806 201.55,82.81 201.66,82.92 205.714,82.92 205.771,82.864 210.548,82.864 210.878,83.194 212.063,83.194 RJ3.D1@212.18,83.077
MTXV_P4_B_N: RJ3.D6 T2.41 | length 18.2
  Top Layer w0.188: T2.41@200.794,86.66 201.324,86.66 201.55,86.434 201.55,86.431 201.66,86.321 205.517,86.321 205.947,85.891 210.052,85.891 211.243,87.081 212.513,87.081 213.176,87.745 213.176,88.57 212.319,89.427 RJ3.D6@209.64,89.427
MTXV_P4_B_P: RJ3.D3 T2.40 | length 13.2
  Top Layer w0.188: T2.40@200.794,85.64 201.324,85.64 201.55,85.866 201.55,85.87 201.66,85.98 205.376,85.98 205.806,85.55 210.193,85.55 211.367,86.724 212.07,86.724 212.18,86.614 RJ3.D3@212.18,85.617
MTXV_P4_C_N: RJ3.D5 T2.44 | length 12
  Top Layer w0.188: T2.44@200.794,89.72 201.324,89.72 201.55,89.494 201.55,89.491 201.66,89.381 205.345,89.381 206.295,88.431 210.505,88.431 210.778,88.157 RJ3.D5@212.18,88.157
